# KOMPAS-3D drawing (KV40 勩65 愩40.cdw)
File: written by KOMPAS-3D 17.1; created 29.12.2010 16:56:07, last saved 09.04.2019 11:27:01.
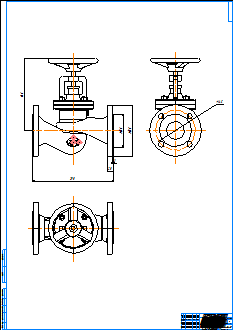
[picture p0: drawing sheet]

Title block, sheet 1: name: KV 40 Ду65; material: Внимание! Данный продукт является объектом авторского права ООО «Торговый Дом АДЛ». / Запрещается изменение, копирование, распространение / (в том числе путем копирования на другие сайты и ресурсы в Интернете) / или любое иное использование информации и объектов без предварительного / согласия правообладателя (ООО «Торговый Дом АДЛ»).; scale: 1:1; sheets: 1; organisation: ООО "Торговый дом АДЛ"; sheet format: A0; stored path: \\adlc.lan\data\АДЛ_ПКД\3D-модели\ADL production\Вентили ГРАНВЕНТ\KV40\KOMPAS 2D\KV 40 Ду65.cdw

Views: Спереди 1, Проекционный вид 2, Проекционный вид 3
Dimensions and other numbers on the sheet: 122; 185; 3; 20; 290; 260; 145; 1:1; 1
